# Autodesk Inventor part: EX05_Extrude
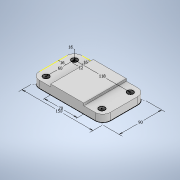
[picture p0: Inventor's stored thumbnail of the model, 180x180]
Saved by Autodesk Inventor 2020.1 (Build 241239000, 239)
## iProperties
Created: 2019-10
Part Number: EX05_Extrude
Material: Generic
Document SubType Name: Modeling
Designer: Synergysoft Dell02
Density: 1 g/cm^3
Appearance: Default
Author: Synergysoft Dell02
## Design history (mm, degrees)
sketch "Sketch1"
  geometry: L1 (59, -45)-(-59, -45); L2 (-75, -29)-(-75, 29); L3 (-59, 45)-(59, 45); L4 (75, 29)-(75, -29); L5 (75, -45)-(-75, 45); L6 (-75, -45)-(75, 45); L7 (35, -45)-(-35, -45); L8 (-35, -45)-(-35, 45); L9 (-35, 45)-(35, 45); L10 (35, 45)-(35, -45); L11 (35, -45)-(-35, 45); L12 (-35, -45)-(35, 45); A1 r 16 centre (59, -29) between (59, -45) and (75, -29); A2 r 16 centre (-59, -29) between (-75, -29) and (-59, -45); A3 r 16 centre (-59, 29) between (-59, 45) and (-75, 29); A4 r 16 centre (59, 29) between (75, 29) and (59, 45); 4 further points
  constraints: 24 end point, 9 point on line, 8 point on circle, 8 tangent, 4 centre point, 4 midpoint, 4 parallel, 3 equal radius, 2 horizontal, 2 perpendicular
  dimensions: "d0" = 150 distance of L5.end L6.end; "d1" = 90 distance of L6.start L5.end; "d2" = 70 distance of L8.end L9.end; "d3" = 16 radius of A1
extrude "Extrusion1" new body sketch "Sketch1" distance "d4" = 15; taper "d5" = 0 deg
extrude "Extrusion2" join sketch "Sketch1" distance "d6" = 20; taper "d7" = 0 deg
sketch "Sketch2"
  geometry: L1 (-75, 29)-(-75, -29) reference; L2 (-35, 45)-(-59, 45) reference; C1 r 6 at (-59, 29); C2 r 6 at (59, 29); C3 r 6 at (-59, -31); C4 r 6 at (59, -31); 1 further point
  constraints: 4 centre point, 1 horizontal, 1 vertical, 6 other
  dimensions: "d8" = 12 diameter of C1; "d9" = 16 distance from line of C1.centre L1; "d10" = 16 distance from line of L2 C1.centre; "d13" = 118 distance of C1.centre C2.centre; "d16" = 60 distance of C1.centre C3.centre
extrude "Extrusion3" cut sketch "Sketch2" stored distance "d19" = 12; taper "d20" = 0 deg
body "Solid1"
